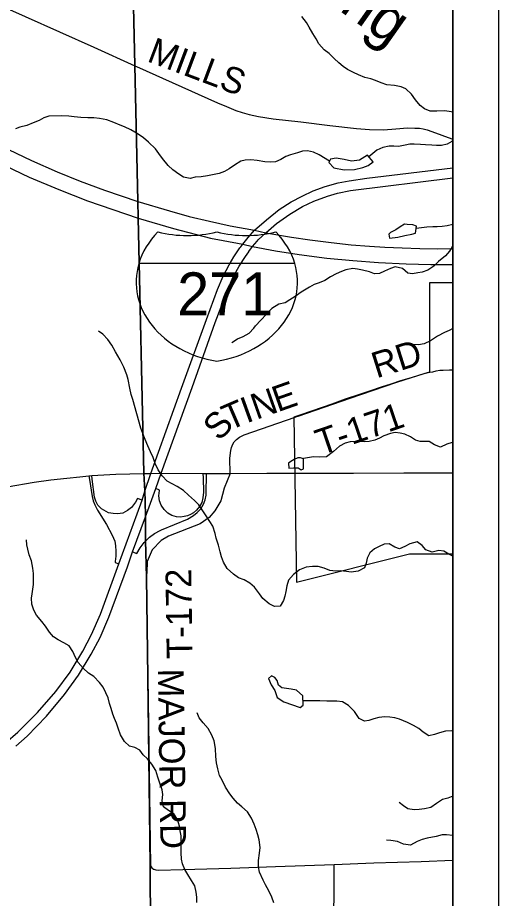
# Model space of a CAD drawing. Extents: x 0 to 34, y 0 to 22.
# Drawn here: x 7.942 to 9, y 17.94 to 19.877 of the extents above; entities that cross this region are included whole.
import ezdxf

# ---------------------------------------------------------------- set-up
doc = ezdxf.new("R2010")
doc.units = 0
for name, color, linetype in [('Default', 7, 'Continuous'), ('GM_X_City_Street', 7, 'Continuous'), ('GM_X_County_Road', 7, 'Continuous'), ('GM_X_County_Road_Text', 7, 'Continuous'), ('GM_X_Interchange_Ramps', 7, 'Continuous'), ('GM_X_Interstate_Location', 7, 'Continuous'), ('GM_X_Interstate_Route', 7, 'Continuous'), ('GM_X_Interstate_Shield', 7, 'Continuous'), ('GM_X_Minor_Lake', 7, 'Continuous'), ('GM_X_Minor_River', 7, 'Continuous'), ('GM_X_Minor_River_Text', 7, 'Continuous'), ('GM_X_State_Route', 7, 'Continuous'), ('GM_X_Township_Road', 7, 'Continuous'), ('GM_X_Township_Road_Text', 7, 'Continuous'), ('SH_Cut_Line', 7, 'Continuous'), ('SH_Data', 7, 'Continuous')]:
    doc.layers.add(name, color=color, linetype=linetype)

msp = doc.modelspace()

# ---------------------------------------------------------------- linework, layer by layer
at = {"layer": 'Default'}
for points in [[(8.9, 15.9304), (8.9, 20.9), (8.1749, 20.9), (8.1859, 20.3892), (8.1995, 19.7718), (8.2061, 19.4737), (8.2069, 19.4369), (8.2195, 18.875), (8.2216, 18.8361), (8.2229, 18.8136), (8.2232, 18.7798), (8.2237, 18.7271), (8.2254, 18.6464), (8.2283, 18.4271), (8.2338, 18.0126), (8.2361, 17.5877), (8.2392, 17.3521), (8.2417, 17.2403), (8.2434, 16.7876), (8.2536, 16.1438), (8.2582, 15.9227), (8.4608, 15.9241), (8.569, 15.9256)], [(8.9, 18.698), (8.9, 19.2942), (8.8485, 19.2939), (8.8485, 19.0972), (8.8336, 19.0928), (8.8101, 19.0858), (8.7844, 19.0781), (8.7632, 19.0714), (8.7423, 19.0644), (8.7164, 19.0558), (8.6918, 19.0476), (8.6631, 19.0378), (8.6333, 19.0274), (8.612, 19.02), (8.5862, 19.011), (8.5652, 19.0037), (8.55, 18.9984), (8.5559, 18.6357), (8.8045, 18.6983)]]:
    msp.add_lwpolyline(points, close=True, dxfattribs=at)
msp.add_lwpolyline([(6.5781, 15.8955), (6.9232, 15.9027), (7.0184, 15.9049), (7.3026, 15.9113), (7.5392, 15.9156), (8.2582, 15.9227), (8.2536, 16.1438), (8.2434, 16.7876), (8.2417, 17.2403), (8.2392, 17.3521), (8.2361, 17.5877), (8.2338, 18.0126), (8.2283, 18.4271), (8.2254, 18.6464), (8.2237, 18.7271), (8.2232, 18.7798), (8.2229, 18.8136), (8.2216, 18.8361), (8.2195, 18.875), (8.2069, 19.4369), (8.2061, 19.4737), (8.1995, 19.7718), (8.1859, 20.3892)], dxfattribs=at)
at = {"layer": 'GM_X_City_Street'}
msp.add_lwpolyline([(8.8489, 19.0976), (8.8556, 19.0985), (8.8632, 19.1004), (8.8708, 19.1015), (8.8782, 19.1022), (8.8924, 19.1027), (8.9, 19.1027)], dxfattribs=at)
at = {"layer": 'GM_X_County_Road'}
for points in [[(7.2787, 20.0387), (7.2914, 20.0361), (7.3003, 20.0341), (7.3119, 20.0299), (7.3218, 20.0262), (7.3317, 20.0232), (7.3469, 20.0198), (7.3596, 20.0183), (7.369, 20.0175), (7.4017, 20.0179), (7.563, 20.0232), (7.5984, 20.023), (7.6086, 20.0228), (7.6222, 20.0221), (7.6305, 20.0212), (7.6401, 20.0198), (7.6547, 20.0163), (7.6676, 20.011), (7.8823, 19.9136), (8.1094, 19.812), (8.1997, 19.7712), (8.2034, 19.7696)], [(8.2034, 19.7696), (8.3819, 19.6897), (8.4018, 19.6814), (8.4225, 19.6726), (8.4361, 19.6687), (8.4517, 19.6639), (8.4718, 19.6595), (8.5045, 19.6549), (8.5651, 19.648), (8.6291, 19.6399), (8.6874, 19.6332), (8.7162, 19.6311), (8.7473, 19.6307), (8.7743, 19.6325), (8.7998, 19.6344), (8.816, 19.6341), (8.8263, 19.6337), (8.8342, 19.6323), (8.8431, 19.6304), (8.8533, 19.6268), (8.8977, 19.6109), (8.9, 19.6103)]]:
    msp.add_lwpolyline(points, dxfattribs=at)
at = {"layer": 'GM_X_Interchange_Ramps'}
for points in [[(8.0988, 18.8695), (8.0999, 18.8613), (8.1056, 18.8242), (8.108, 18.8146), (8.1116, 18.8059), (8.1179, 18.7938), (8.1377, 18.7626), (8.1502, 18.739), (8.1556, 18.726), (8.1574, 18.7158), (8.1584, 18.704), (8.1579, 18.6928), (8.1568, 18.6812), (8.1563, 18.6792), (8.1648, 18.6761)], [(8.1201, 18.8037), (8.1188, 18.8052), (8.1139, 18.8135), (8.1114, 18.8227), (8.1061, 18.8618), (8.1053, 18.8701)], [(8.3496, 18.8748), (8.3499, 18.8651), (8.3508, 18.8335), (8.3494, 18.821), (8.3474, 18.8109), (8.3424, 18.8019), (8.3358, 18.7943), (8.3289, 18.7883), (8.3221, 18.7844), (8.316, 18.7817), (8.3088, 18.78), (8.3005, 18.7787), (8.2919, 18.779), (8.2816, 18.7821), (8.2726, 18.7873), (8.2644, 18.7956), (8.2578, 18.8052), (8.2539, 18.8144), (8.2529, 18.8253), (8.2539, 18.8375), (8.254, 18.8383), (8.246, 18.8418)], [(8.2558, 18.7491), (8.2584, 18.7505), (8.3158, 18.7742), (8.3288, 18.782), (8.3374, 18.7886), (8.3449, 18.7971), (8.3508, 18.807), (8.3547, 18.8165), (8.3566, 18.8269), (8.3568, 18.8395), (8.3573, 18.8652), (8.3573, 18.8748)], [(8.2159, 18.8158), (8.206, 18.8196), (8.2015, 18.8115), (8.1927, 18.7999), (8.184, 18.793), (8.1737, 18.7876), (8.1615, 18.7861), (8.1523, 18.7866), (8.142, 18.7881), (8.1262, 18.7969), (8.1201, 18.8037)], [(8.2232, 18.7258), (8.2239, 18.7265), (8.2318, 18.7347), (8.2433, 18.7426), (8.2558, 18.7491)], [(8.1947, 18.7022), (8.2044, 18.6986), (8.2116, 18.7114), (8.2205, 18.723), (8.2232, 18.7258)]]:
    msp.add_lwpolyline(points, dxfattribs=at)
at = {"layer": 'GM_X_Interstate_Route'}
for points in [[(7.763, 19.6693), (7.7803, 19.6592), (7.8872, 19.6029), (7.9722, 19.5629), (8.0288, 19.5381), (8.0798, 19.5173), (8.133, 19.4976), (8.2063, 19.4731), (8.2759, 19.4521), (8.3193, 19.44), (8.3644, 19.4294), (8.4096, 19.4189), (8.4631, 19.4094), (8.4883, 19.4042), (8.5449, 19.3944), (8.5849, 19.3884), (8.632, 19.3823), (8.676, 19.3776), (8.7165, 19.3744), (8.7499, 19.3726), (8.7881, 19.3707), (8.827, 19.3697), (8.8657, 19.3686), (8.9, 19.3694)], [(7.77, 19.6256), (7.777, 19.6216), (7.8775, 19.5687), (7.967, 19.5263), (8.0323, 19.4989), (8.096, 19.4742), (8.2071, 19.4363), (8.2852, 19.4131), (8.3666, 19.3924), (8.3941, 19.3871)], [(8.4329, 19.3732), (8.4373, 19.3789), (8.4493, 19.3933), (8.4631, 19.4094), (8.4893, 19.4324), (8.5176, 19.4549), (8.5439, 19.4718), (8.5678, 19.4847), (8.5924, 19.4961), (8.6187, 19.506), (8.6473, 19.5139), (8.6719, 19.5184), (8.7107, 19.5238), (8.9, 19.5468)], [(8.469, 19.3853), (8.4716, 19.3881), (8.4883, 19.4042), (8.5114, 19.4242), (8.5409, 19.4452), (8.5688, 19.4617), (8.5939, 19.4734), (8.6241, 19.4848), (8.6458, 19.4909), (8.6742, 19.497), (8.9, 19.5248)], [(8.2159, 18.8158), (8.2218, 18.8356), (8.2352, 18.8747), (8.3029, 19.0625), (8.3575, 19.2133), (8.3817, 19.2793), (8.3942, 19.3087), (8.4074, 19.3335), (8.4177, 19.3514), (8.431, 19.3707), (8.4329, 19.3732)], [(8.3941, 19.3871), (8.4373, 19.3789), (8.4586, 19.374), (8.5095, 19.3642), (8.5613, 19.3563), (8.6221, 19.3484), (8.68, 19.3429), (8.7363, 19.3387), (8.7971, 19.3355), (8.8511, 19.3345), (8.9, 19.3345)], [(8.4504, 19.3621), (8.451, 19.363), (8.4563, 19.3706)], [(8.4563, 19.3706), (8.4586, 19.374), (8.469, 19.3853)], [(7.9379, 18.2751), (7.9628, 18.2973), (8.0057, 18.3409), (8.0448, 18.3884), (8.0761, 18.4311), (8.1039, 18.4772), (8.1234, 18.514), (8.143, 18.5584), (8.1835, 18.6694), (8.1947, 18.7022), (8.2234, 18.7793), (8.2341, 18.8095), (8.246, 18.8418), (8.258, 18.8751), (8.3259, 19.0634), (8.3767, 19.2064), (8.4029, 19.2753), (8.4159, 19.3053), (8.4293, 19.3306), (8.4436, 19.3517), (8.4504, 19.3621)], [(7.1051, 17.9225), (7.2044, 17.9618), (7.2972, 17.9988), (7.4555, 18.0618), (7.6271, 18.1297), (7.7081, 18.1617), (7.7533, 18.1809), (7.7907, 18.1993), (7.8258, 18.2185), (7.8572, 18.2381), (7.8837, 18.2574), (7.9154, 18.2825), (7.9424, 18.306), (7.9856, 18.3489), (8.0262, 18.3952), (8.0574, 18.4379), (8.0852, 18.484), (8.1047, 18.5208), (8.1243, 18.5652), (8.1648, 18.6761), (8.2052, 18.7856), (8.2159, 18.8158)]]:
    msp.add_lwpolyline(points, dxfattribs=at)
at = {"layer": 'GM_X_Interstate_Shield'}
msp.add_line((8.552, 19.3361), (8.2087, 19.3361), dxfattribs=at)
msp.add_line((8.552, 19.3361), (8.2087, 19.3361), dxfattribs=at)
for centre, start_param, end_param in [((8.4247, 19.2956), 2.47259, 2.911027), ((8.3155, 19.5755), 4.415841, 5.008937), ((8.4452, 19.5755), 4.415841, 5.008937), ((8.3359, 19.2956), 0.230566, 0.669003), ((8.4247, 19.2956), 2.911027, 4.511031), ((8.3359, 19.2956), 4.913747, 6.513751)]:
    msp.add_ellipse(centre, major_axis=(0.2219, 0), ratio=0.8, start_param=start_param, end_param=end_param, dxfattribs=at)
at = {"layer": 'GM_X_Minor_Lake'}
for points in [[(8.7121, 19.5744), (8.694, 19.5636), (8.6769, 19.5615), (8.6602, 19.5648), (8.6431, 19.5677), (8.6306, 19.5657), (8.6265, 19.5584), (8.6376, 19.5471), (8.6608, 19.5424), (8.6835, 19.543), (8.7017, 19.5477), (8.7134, 19.552), (8.7247, 19.5601)], [(8.7247, 19.5601), (8.7121, 19.5744)], [(8.8199, 19.4185), (8.8116, 19.4215), (8.7994, 19.4225), (8.793, 19.4228), (8.7835, 19.4174), (8.7745, 19.4101), (8.7628, 19.4043), (8.7587, 19.4008), (8.7603, 19.3921), (8.7788, 19.3946), (8.7939, 19.3978), (8.8098, 19.4006), (8.8173, 19.4029)], [(8.8173, 19.4029), (8.8199, 19.4185)], [(8.5712, 18.9072), (8.5643, 18.9094), (8.5583, 18.9094), (8.5507, 18.9055), (8.5432, 18.9012), (8.5379, 18.897), (8.5388, 18.886), (8.5494, 18.8872), (8.5592, 18.8873), (8.5661, 18.8825), (8.571, 18.8848)], [(8.571, 18.8848), (8.5712, 18.9072)], [(8.5696, 18.3854), (8.5554, 18.3978), (8.544, 18.4003), (8.5334, 18.4021), (8.5232, 18.4035), (8.5163, 18.4092), (8.5128, 18.4194), (8.5078, 18.4258), (8.5006, 18.4295), (8.4942, 18.4238), (8.4996, 18.4098), (8.5077, 18.3977), (8.5131, 18.3822), (8.528, 18.3724), (8.5637, 18.3602), (8.57, 18.3655)], [(8.57, 18.3655), (8.5696, 18.3854)]]:
    msp.add_lwpolyline(points, dxfattribs=at)
at = {"layer": 'GM_X_Minor_River'}
for points in [[(8.9, 19.6695), (8.8958, 19.6696), (8.8822, 19.6718), (8.8647, 19.6712), (8.8496, 19.6715), (8.8374, 19.6763), (8.8275, 19.6838), (8.8175, 19.6963), (8.8087, 19.7087), (8.7961, 19.7204), (8.7862, 19.7252), (8.771, 19.7277), (8.7543, 19.7295), (8.7421, 19.7335), (8.7296, 19.7391), (8.7189, 19.7424), (8.7064, 19.7457), (8.6923, 19.7513), (8.6813, 19.7565), (8.668, 19.7632), (8.6584, 19.7696), (8.6489, 19.7779), (8.6386, 19.7873), (8.6279, 19.7982), (8.6168, 19.8064), (8.6049, 19.8196), (8.5988, 19.8302), (8.5915, 19.8419), (8.5834, 19.8559), (8.5776, 19.8665), (8.5673, 19.8793)], [(8.6285, 19.5618), (8.6055, 19.5753), (8.5934, 19.5813), (8.5801, 19.5842), (8.5691, 19.5833), (8.5577, 19.5798), (8.5426, 19.5755), (8.5324, 19.5719), (8.5211, 19.5654), (8.5094, 19.5603), (8.4984, 19.5591), (8.4863, 19.5601), (8.4688, 19.5626), (8.4551, 19.5644), (8.4426, 19.5639), (8.4328, 19.5611), (8.4192, 19.5526), (8.4075, 19.5449), (8.397, 19.5384), (8.3853, 19.5341), (8.3705, 19.5313), (8.3595, 19.5293), (8.3459, 19.5272), (8.3327, 19.526), (8.3213, 19.5236), (8.3073, 19.5261), (8.2966, 19.5328), (8.2832, 19.5426), (8.2733, 19.5516), (8.2607, 19.5671), (8.253, 19.578), (8.2453, 19.5886), (8.23, 19.6033), (8.2193, 19.613), (8.2052, 19.622), (8.1911, 19.6306), (8.1774, 19.637), (8.1679, 19.6403), (8.1538, 19.6466), (8.1379, 19.6522), (8.1219, 19.655), (8.1098, 19.6564), (8.0961, 19.6567), (8.081, 19.6573), (8.0665, 19.6591), (8.0548, 19.6605), (8.0381, 19.6615), (8.0108, 19.6604), (7.9999, 19.6569), (7.9893, 19.6511), (7.9764, 19.6457), (7.9621, 19.6402), (7.947, 19.6359), (7.9371, 19.6328)], [(8.9, 19.6064), (8.8975, 19.6047), (8.887, 19.5985), (8.8749, 19.5957), (8.8639, 19.5956), (8.8533, 19.5963), (8.8396, 19.5973), (8.8282, 19.5983), (8.8149, 19.5986), (8.8051, 19.5989), (8.7949, 19.5965), (8.7805, 19.5937), (8.7699, 19.5947), (8.7596, 19.5946), (8.7456, 19.5918), (8.7328, 19.5856), (8.715, 19.5711)], [(8.9, 19.4219), (8.887, 19.4192), (8.876, 19.4179), (8.865, 19.4171), (8.8556, 19.4173), (8.8423, 19.4165), (8.819, 19.4134)], [(8.9, 19.3769), (8.898, 19.3733), (8.8924, 19.3634), (8.8838, 19.3534), (8.8683, 19.3411), (8.8578, 19.3307), (8.845, 19.3215), (8.8325, 19.3176), (8.8227, 19.316), (8.8113, 19.314), (8.8007, 19.3154), (8.7893, 19.3255), (8.7726, 19.3288), (8.7627, 19.3253), (8.7495, 19.3194), (8.7382, 19.3144), (8.7272, 19.3139), (8.7162, 19.318), (8.7006, 19.322), (8.6896, 19.3242), (8.6793, 19.3256), (8.6646, 19.3228), (8.6548, 19.3185), (8.6427, 19.3139), (8.6306, 19.3069), (8.6178, 19.2992), (8.6053, 19.2941), (8.5947, 19.2899), (8.5842, 19.2844), (8.5661, 19.2736), (8.5529, 19.2636), (8.5412, 19.2567), (8.5306, 19.2501), (8.517, 19.2469), (8.5012, 19.2373), (8.4895, 19.225), (8.4775, 19.2116), (8.4651, 19.1993)], [(8.4136, 19.1628), (8.426, 19.1705), (8.4381, 19.176), (8.4517, 19.1829), (8.4618, 19.1944), (8.4651, 19.1993)], [(8.1952, 19.0373), (8.1917, 19.0483), (8.1885, 19.062), (8.1849, 19.0813), (8.1822, 19.0919), (8.1756, 19.1082), (8.1675, 19.1244), (8.1571, 19.1422), (8.149, 19.1565), (8.1402, 19.169), (8.1295, 19.181), (8.12, 19.1878)], [(8.9, 19.1933), (8.8917, 19.189), (8.8815, 19.1847), (8.8661, 19.1766), (8.8506, 19.1666), (8.8363, 19.16), (8.8238, 19.1572), (8.809, 19.1582), (8.7961, 19.1615)], [(8.2599, 18.8697), (8.2511, 18.8825), (8.2445, 18.8969), (8.2399, 18.9098), (8.2344, 18.9222), (8.2283, 18.9355), (8.2228, 18.9491), (8.2178, 18.9623), (8.2131, 18.9745), (8.1952, 19.0373)], [(8.9, 18.9419), (8.898, 18.9426), (8.8867, 18.9391), (8.8723, 18.9325), (8.8594, 18.9373), (8.8479, 18.9448), (8.8373, 18.9451), (8.8279, 18.945), (8.8176, 18.9479), (8.8069, 18.955), (8.7944, 18.9614), (8.7837, 18.9635), (8.7727, 18.9646), (8.7625, 18.9626), (8.7478, 18.9575), (8.738, 18.9525), (8.7281, 18.9478), (8.7153, 18.945), (8.705, 18.9446), (8.6948, 18.9448), (8.6736, 18.9439), (8.663, 18.9415), (8.6502, 18.9349), (8.637, 18.923), (8.6216, 18.9115), (8.6064, 18.9106), (8.5931, 18.9112), (8.571, 18.9073)], [(8.9, 18.6928), (8.891, 18.6972), (8.88, 18.7035), (8.8689, 18.7053), (8.8546, 18.7018), (8.8401, 18.7066), (8.8325, 18.7164), (8.821, 18.7242), (8.8048, 18.7203), (8.7938, 18.7141), (8.7821, 18.7091), (8.7719, 18.7124), (8.7593, 18.7202), (8.7483, 18.7194), (8.7377, 18.7143), (8.7275, 18.7093), (8.717, 18.7001), (8.7114, 18.6886), (8.7092, 18.6776), (8.7055, 18.6669), (8.6912, 18.66), (8.676, 18.6579), (8.6658, 18.6593), (8.6521, 18.6607), (8.6423, 18.6595), (8.629, 18.6613), (8.6168, 18.6665), (8.6031, 18.6701), (8.5906, 18.67), (8.5766, 18.6684), (8.5619, 18.6629), (8.5487, 18.6525), (8.5382, 18.6403), (8.5345, 18.6277), (8.5324, 18.6155), (8.5298, 18.6049), (8.5272, 18.5954), (8.5197, 18.5831), (8.5076, 18.5819), (8.4954, 18.5882), (8.4817, 18.5995), (8.4744, 18.6101), (8.4633, 18.6244), (8.453, 18.6334), (8.4408, 18.6405), (8.4282, 18.6453), (8.4168, 18.6532), (8.403, 18.6656), (8.395, 18.6796), (8.3903, 18.6913), (8.3879, 18.7027), (8.3837, 18.717), (8.379, 18.7326), (8.377, 18.7424), (8.3715, 18.7587), (8.3646, 18.7689), (8.3581, 18.7795), (8.3493, 18.7927), (8.3408, 18.8055), (8.3313, 18.8149), (8.3183, 18.8273), (8.3072, 18.8375), (8.2931, 18.8457), (8.2817, 18.852), (8.271, 18.8576), (8.2599, 18.8697)], [(8.3362, 17.9316), (8.3361, 17.9433), (8.3352, 17.9536), (8.3317, 17.9676), (8.3248, 17.9793), (8.3163, 17.9925), (8.3101, 18.0035), (8.3047, 18.0164), (8.3024, 18.0262), (8.3019, 18.0403), (8.3022, 18.052), (8.302, 18.0672), (8.3016, 18.0775), (8.2999, 18.0892), (8.298, 18.0991), (8.2937, 18.1135), (8.286, 18.1263), (8.2738, 18.1334), (8.2631, 18.1417), (8.26, 18.1549), (8.2614, 18.169), (8.2601, 18.1789), (8.2547, 18.194), (8.2504, 18.2072), (8.2461, 18.2213), (8.2373, 18.2352), (8.2281, 18.2473), (8.2182, 18.2559), (8.2109, 18.2661), (8.1998, 18.2721), (8.1884, 18.275), (8.177, 18.2852), (8.1685, 18.3003), (8.1635, 18.3143), (8.1592, 18.3256), (8.1549, 18.3359), (8.1514, 18.3457), (8.1475, 18.3582), (8.1444, 18.3688), (8.1409, 18.3813), (8.1363, 18.3923), (8.1305, 18.4047), (8.1224, 18.4153), (8.1094, 18.4285), (8.098, 18.4356), (8.0858, 18.4465), (8.0754, 18.4589), (8.0696, 18.4699), (8.0635, 18.4831), (8.0554, 18.4959), (8.0436, 18.5023), (8.0314, 18.5086), (8.0207, 18.5154), (8.0119, 18.5259), (8.0035, 18.5387), (7.995, 18.5489), (7.9832, 18.5629), (7.9778, 18.5738), (7.9731, 18.5871), (7.9722, 18.6004), (7.9737, 18.6099), (7.9751, 18.6201), (7.9765, 18.6308), (7.9772, 18.6437), (7.9771, 18.6547), (7.9755, 18.6668), (7.9727, 18.6828), (7.9676, 18.6956), (7.9641, 18.7085), (7.9625, 18.718), (7.9617, 18.729)], [(8.9, 18.3081), (8.8966, 18.3091), (8.8837, 18.3082), (8.8701, 18.3047), (8.8595, 18.3004), (8.8467, 18.2976), (8.8345, 18.3058), (8.8249, 18.3137), (8.8131, 18.3204), (8.8002, 18.3272), (8.7827, 18.3346), (8.772, 18.3375), (8.7614, 18.3389), (8.75, 18.3392), (8.7371, 18.338), (8.7262, 18.3352), (8.7148, 18.3317), (8.705, 18.3301), (8.6936, 18.3356), (8.6836, 18.3511), (8.6702, 18.3647), (8.6569, 18.3725), (8.6443, 18.3743), (8.633, 18.3738), (8.6224, 18.3737), (8.6072, 18.3747), (8.5935, 18.3749), (8.5698, 18.375)], [(8.5056, 17.9305), (8.5013, 17.943), (8.4948, 17.957), (8.4871, 17.9702), (8.4821, 17.9801), (8.4743, 17.9978), (8.4723, 18.0096), (8.4718, 18.0236), (8.474, 18.0396), (8.4754, 18.0522), (8.4733, 18.0688), (8.4702, 18.0802), (8.4671, 18.0919), (8.4628, 18.1037), (8.4566, 18.1169), (8.4478, 18.1305), (8.4352, 18.1414), (8.4256, 18.15), (8.4165, 18.1606), (8.4088, 18.1704), (8.3996, 18.1851), (8.3922, 18.2002), (8.3865, 18.2108), (8.3822, 18.2252), (8.3794, 18.2385), (8.3778, 18.2525), (8.3772, 18.27), (8.3748, 18.2867), (8.3694, 18.2995), (8.3609, 18.3139), (8.3506, 18.3263), (8.3418, 18.3376), (8.3368, 18.3482)], [(8.9, 18.1651), (8.8888, 18.1609), (8.8767, 18.1574), (8.8638, 18.1493), (8.851, 18.14), (8.837, 18.1372), (8.8253, 18.1356), (8.8147, 18.1351), (8.801, 18.1373), (8.7911, 18.1436), (8.7816, 18.1508)], [(8.9, 18.0784), (8.886, 18.08), (8.8762, 18.0799), (8.8633, 18.0767), (8.8433, 18.0724), (8.8319, 18.0696), (8.821, 18.0657), (8.8066, 18.0576), (8.7911, 18.0593), (8.7778, 18.0657), (8.763, 18.0678), (8.7535, 18.0685)]]:
    msp.add_lwpolyline(points, dxfattribs=at)
at = {"layer": 'GM_X_State_Route'}
for p, q in [((8.5806, 18.8754), (8.6812, 18.8757)), ((8.6812, 18.8757), (8.7918, 18.8761))]:
    msp.add_line(p, q, dxfattribs=at)
for points in [[(7.9191, 18.8456), (7.9785, 18.8559), (8.0152, 18.8608), (8.05, 18.8645), (8.0785, 18.8674)], [(8.0785, 18.8674), (8.0988, 18.8695), (8.1053, 18.8701), (8.1581, 18.8735), (8.2197, 18.8744), (8.2352, 18.8747), (8.258, 18.8751), (8.3496, 18.8748), (8.3573, 18.8748), (8.41, 18.8745), (8.4903, 18.875)], [(8.4903, 18.875), (8.5524, 18.8753), (8.5806, 18.8754)], [(8.7918, 18.8761), (8.827, 18.8762), (8.9, 18.8762)]]:
    msp.add_lwpolyline(points, dxfattribs=at)
at = {"layer": 'GM_X_Township_Road'}
msp.add_line((8.227, 18.6759), (8.2257, 18.6468), dxfattribs=at)
for points in [[(8.5591, 19.0009), (8.6738, 19.04), (8.7767, 19.0752), (8.839, 19.0953), (8.8489, 19.0976)], [(8.4348, 18.9567), (8.4403, 18.9593), (8.5524, 18.9986), (8.5563, 18.9999), (8.5591, 19.0009)], [(8.41, 18.8745), (8.4089, 18.9087), (8.411, 18.9253), (8.4124, 18.9317), (8.4153, 18.9391), (8.4188, 18.9442), (8.4234, 18.9492), (8.4302, 18.9545), (8.4348, 18.9567)], [(8.41, 18.8745), (8.3962, 18.8424), (8.3894, 18.8142), (8.3758, 18.7927), (8.3638, 18.7778), (8.3439, 18.7639), (8.274, 18.737), (8.2576, 18.7272), (8.238, 18.7064), (8.2272, 18.6808), (8.227, 18.6759)], [(8.2257, 18.6468), (8.2256, 18.6458), (8.2285, 18.4265), (8.234, 18.0121), (8.2371, 18.0076), (8.2411, 18.0049), (8.2419, 18.0046)], [(8.2419, 18.0046), (8.2459, 18.0029), (8.252, 18.0026), (8.3052, 18.004), (8.4112, 18.0068), (8.5092, 18.0104), (8.6382, 18.015), (8.7259, 18.0185), (8.8298, 18.0215), (8.9, 18.0241)], [(8.6381, 17.8456), (8.6382, 18.015)]]:
    msp.add_lwpolyline(points, dxfattribs=at)
at = {"layer": 'SH_Cut_Line'}
msp.add_lwpolyline([(3.2807, 14.1), (8.9, 14.1), (8.9, 20.9), (3.2826, 20.9), (3.2843, 20.6124), (3.2845, 20.5998), (3.2888, 19.8918), (3.2901, 19.68), (3.2904, 19.1173), (3.2907, 18.4315), (3.2837, 17.3796), (3.2835, 17.0107), (3.2832, 16.3898), (3.2829, 15.8433), (3.2815, 15.7537), (3.2811, 15.7294), (3.2832, 14.8896), (3.2841, 14.501), (3.2822, 14.2781), (3.2808, 14.1155)], close=True, dxfattribs=at)
at = {"layer": 'SH_Data'}
for p, q in [((9, 21), (9, 14)), ((8.9, 20.9), (8.9, 14.1))]:
    msp.add_line(p, q, dxfattribs=at)

# ---------------------------------------------------------------- texts
at = {"layer": 'GM_X_County_Road_Text'}
msp.add_text('MILLS', height=0.05682, rotation=339.3901, dxfattribs=at).set_placement((8.2245, 19.7817))
at = {"layer": 'GM_X_Interstate_Location'}
for s in ['.', '-', ',']:
    msp.add_text(s, height=0.000189, dxfattribs=at).set_placement((8.3803, 19.2695))
msp.add_text('271', height=0.000189, rotation=0, dxfattribs=at).set_placement((8.3225, 19.2303))
at = {"layer": 'GM_X_Interstate_Shield'}
msp.add_text('271', height=0.0947, dxfattribs=at).set_placement((8.2931, 19.2222))
at = {"layer": 'GM_X_Minor_River_Text'}
msp.add_text('Spring', height=0.09475, rotation=324.8242, dxfattribs=at).set_placement((8.4634, 20.0235))
at = {"layer": 'GM_X_Township_Road_Text'}
for s, height, rotation, p in [('RD', 0.05682, 17.5018, (8.7318, 19.0836)), ('E', 0.0568, 19.4243, (8.5144, 19.0091)), ('N', 0.0568, 19.4453, (8.4673, 18.9925)), ('I', 0.0568, 19.9064, (8.4455, 18.9846)), ('T', 0.0568, 23.2475, (8.4072, 18.9681)), ('T-171', 0.05682, 18.8785, (8.6094, 18.9142)), ('S', 0.0568, 45.9509, (8.3854, 18.9439)), ('T-172', 0.05682, 90.8431, (8.3269, 18.4673)), ('MAJOR RD', 0.05682, 270.8205, (8.2506, 18.4453))]:
    msp.add_text(s, height=height, rotation=rotation, dxfattribs=at).set_placement(p)

doc.saveas('drawing.dxf')
